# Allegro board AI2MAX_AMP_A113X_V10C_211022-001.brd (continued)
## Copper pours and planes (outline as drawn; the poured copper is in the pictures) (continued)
N21715405 on BOTTOM: 103.9,24.3 111.8,24.3 112.2,23.9 112.2,23 111.5,22.3 104.5,22.3 103.9,22.9
N21715413 on BOTTOM: 105.4,35.9 105.4,34.2 106.3,33.3 106.3,26.4 107.7,25 111.9,25 112.3,25.4 112.3,26.6 111.9,27 109.7,27 108.8,27.9 108.8,33.3 106.2,35.9
N21715441 on TOP: 94.75,23.2 97.6,23.2 97.75,23.35 97.75,28.35 97.6,28.5 94.75,28.5 94.6,28.35 94.6,23.35
N21715900 on TOP: 94.75,35.75 97.6,35.75 97.75,35.9 97.75,40.9 97.6,41.05 94.75,41.05 94.6,40.9 94.6,35.9
N21722582 on TOP: 19.45,34.7 22.3,34.7 22.45,34.85 22.45,39.85 22.3,40 19.45,40 19.3,39.85 19.3,34.85
N21723040 on TOP: 22.45,27.5 22.45,22.3 22.3,22.15 19.45,22.15 19.3,22.3 19.3,27.5
N21723435 on BOTTOM: 5.2,23.8 6.5,23.8 9.2,26.5 9.2,37.8 9.5,38.1 11.2,38.1 11.2,25.8 7.3,21.9 5.2,21.9 4.8,22.3 4.8,23.4
N21723437 on BOTTOM: 13.2,23.2 9.2,23.2 7.1,21.1 5.2,21.1 4.3,22 4.3,23.8 4.9,24.4 6.4,24.4 6.7,24.7 6.7,26.1 6.4,26.4 4.3,26.4 2.2,24.3 2.2,20.8 4.4,18.6 7.7,18.6 10.1,21 12.8,21 13.2,21.4
N21723451 on BOTTOM: 6.4,29.8 6.4,38 6.2,38.2 4.6,38.2 4.4,38 4.4,29.9 4.9,29.4 6,29.4
N21723475 on BOTTOM: 7,38.2 8.5,38.2 8.8,37.9 8.8,28.2 7.4,26.8 5,26.8 4.7,27.1 4.7,28.4 5.1,28.8 6.5,28.8 6.8,29.1 6.8,38
N21723494 on TOP: 19.45,56.65 22.3,56.65 22.45,56.8 22.45,61.8 22.3,61.95 19.45,61.95 19.3,61.8 19.3,56.8
N21724007 on TOP: 19.45,44.1 22.3,44.1 22.45,44.25 22.45,49.3 22.3,49.45 19.45,49.45 19.3,49.3 19.3,44.25
N21727322 on TOP: 87.7,7.2 87.7,15.4 90.15,17.85 93.4,17.85 94.2,17.05 94.2,15.8 93.45,15.05 91.95,15.05 90.8,13.9 90.8,11 91.3,10.5 91.3,7.2
N21727332 on TOP: 87.7,5.1 87.7,1.9 92.95,1.9 95.8,4.75 95.8,11.65 93.5,13.95 92.15,13.95 91.4,13.2 91.4,11.4 92,10.8 92,6.2 90.9,5.1
N22093750 on BOTTOM (solid shape): 101.8,45.85 101.3,45.35 99.8,45.35 99.8,47.85 101.8,47.85
N22093974 on BOTTOM: 108.4,54.2 110.4,54.2 110.4,51.7 108.8,51.7 108.4,52.1
N22094186 on BOTTOM: 99.8,26 99.8,23.6 101.5,23.6 101.8,23.9 101.8,26
N22099090 on BOTTOM: 15.2,37.2 17.3,37.2 17.3,39.7 15.6,39.7 15.2,39.3
N22099146 on BOTTOM: 15.2,25.2 17,25.2 17,22.9 15.5,22.9 15.2,23.2
N22099525 on BOTTOM: 9.9,58 7.4,58 7.2,57.8 7.2,56.3 7.4,56.1 9.9,56.1
N22099581 on BOTTOM (solid shape): 11.5,44.3 10.5,44.3 10.3,44.5 10.3,48 10.5,48.2 11.5,48.2
N22143759 on TOP: 14.55,13.1 14.55,12.2 14.9,11.85 16.2,11.85 18.15,13.8 21.85,13.8 21.9,13.75 21.9,11.6 18.55,11.6 17.1,10.15 14.75,10.15 13.75,11.15 13.75,13.05 13.8,13.1

Small or netless copper shapes (teardrops, artwork), in the pictures only: 1 on BOTTOM, 1 on MID1(L2), 1 on MID2(L3)

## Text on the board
BOTTOM: BOTTOM
Board Geometry/Soldermask Bottom: BOTTOM_SOLDERMASK
Ref Des/Silkscreen Bottom: NC | TD1 | TEN | TD0 | RD0 | RD1 | RCK | RDV | MIO | MDC | GND | VDD | VCC 3.3V | SPI_CLK | SPI_MOSI | SPI_MISO | SPI_SS | BL_EN | BL_PWM | LINE_OUT | RESET | I2C_SCK | I2C_SDA | AMP_RES | VDD 3.3V | AMP_DATA | AMP_BCLK | AMP_WCK | AMP_SCL | AMP_SDA | BOTTOM_SILKSCREEN
User.Comments: CR_UNNAMED_2 | 12.PCB Outline Dimension Tol: | 10.MATERIAL : | 11.PLATING : | 1. PCB VENDOR MUST BE UL  QUALIFIED | 2. BOARD MUST BE IDENTIFIED WITH APPROPRIATE VENDOR UL IDENTIFACTION MARK,DATE CODE | 3. PCB MATERIAL UL FLAMMIBILITY RATING(94V-0 MINIMUM) | 4. ALL DIMESION TOLERANCE AS BELOW UNLESS OTHERWISE SPECIFIED. | 5. PCB LAYERS : | 6. PCB THICKNESS : | 7. | 8. TOP SIDE SILKSCREEN : | 9. SOLDER MASK : | NOTES: | TRACE WIDTHS TO BE FINISHED SIZES+/-1MIL | BOTTOM SIDE SILKSCREEN: | 0.7mil(min) | Prepreg | Copper | Core | OSP 0.2-0.6um[8-24uinch]) | Top(L1) | Mid2(L3) | Bot(L4) | Mid1(L2) | FR4 | 4 LAYERs | GREEN | 1.6 mm+/-0.15 mm | TG: | ,BOTH SIDES | WHITE | 150 | 0.038 mm (H/1oz Finished) | 0.08 mm | 0.03 mm (1oz) | 1.274 mm | 0.015 mm | ROUTING : | CELSIUS | +/- 0.13mm | 1.6+/-0.15mm
TOP: TOP
Board Geometry/Soldermask Top: TOP_SOLDERMASK
Ref Des/Silkscreen Top: Label | 1 | 4 | AI2MAX AMP A113X REV1.0C | TOP_SILKSCREEN
MID1(L2): MID1(L2)
MID2(L3): MID2(L3)
PAGE_OUTLINE: Scale 1000mil | Layer name | PCB P/N | Rev. | Foxconn/CNSBG | 308.03524 | 015
DIMENSION: Prepreg | Copper | Core | Top(L1) | Mid2(L3) | Bot(L4) | Mid1(L2) | 0.038 mm (H/1oz Finished) | 0.08 mm | 0.03 mm (1oz) | 1.274 mm | 0.015 mm | 1.6+/-0.15mm | F
PLACE_BOUND_BOTTOM: 1 | Bottom Side Reflow | 0 degree | Top Side Reflow | 180 degree | Cavity_Number | *Reference CNSBG Break-Away rule | Unit:MM
User.15: MID3(L4)
User.16: MID4(L5)
User.17: MID5(L6)
User.18: MID6(L7)
User.19: MID7(L8)
User.20: MID8(L9)
User.21: MID9(L10)
User.22: MID11(L12)
User.23: MID12(L13)
User.26: BOTTOM_PASTE
User.27: TOP_PASTE
User.30: NCDRILL
User.32: BOTTOM_ASSEMBLY
User.33: TOP_ASSEMBLY
User.34: BOTTOM_ASSEMBLY
User.43: FIGURE | SIZE | 0.2 | 0.25 | 0.254 | 0.4064 | 1.0 | 1.1 | 1.8001 | 4.2 | 0.5 | 0.6 | 2.5 | DRILL CHART: TOP to BOTTOM | ALL UNITS ARE IN MILLIMETERS | TOLERANCE | +0.0762/-0.0762 | +0.0/-0.0 | PLATED | NON-PLATED | QTY | 429 | 1272 | 9 | 2 | 8 | 4 | 60 | 24
